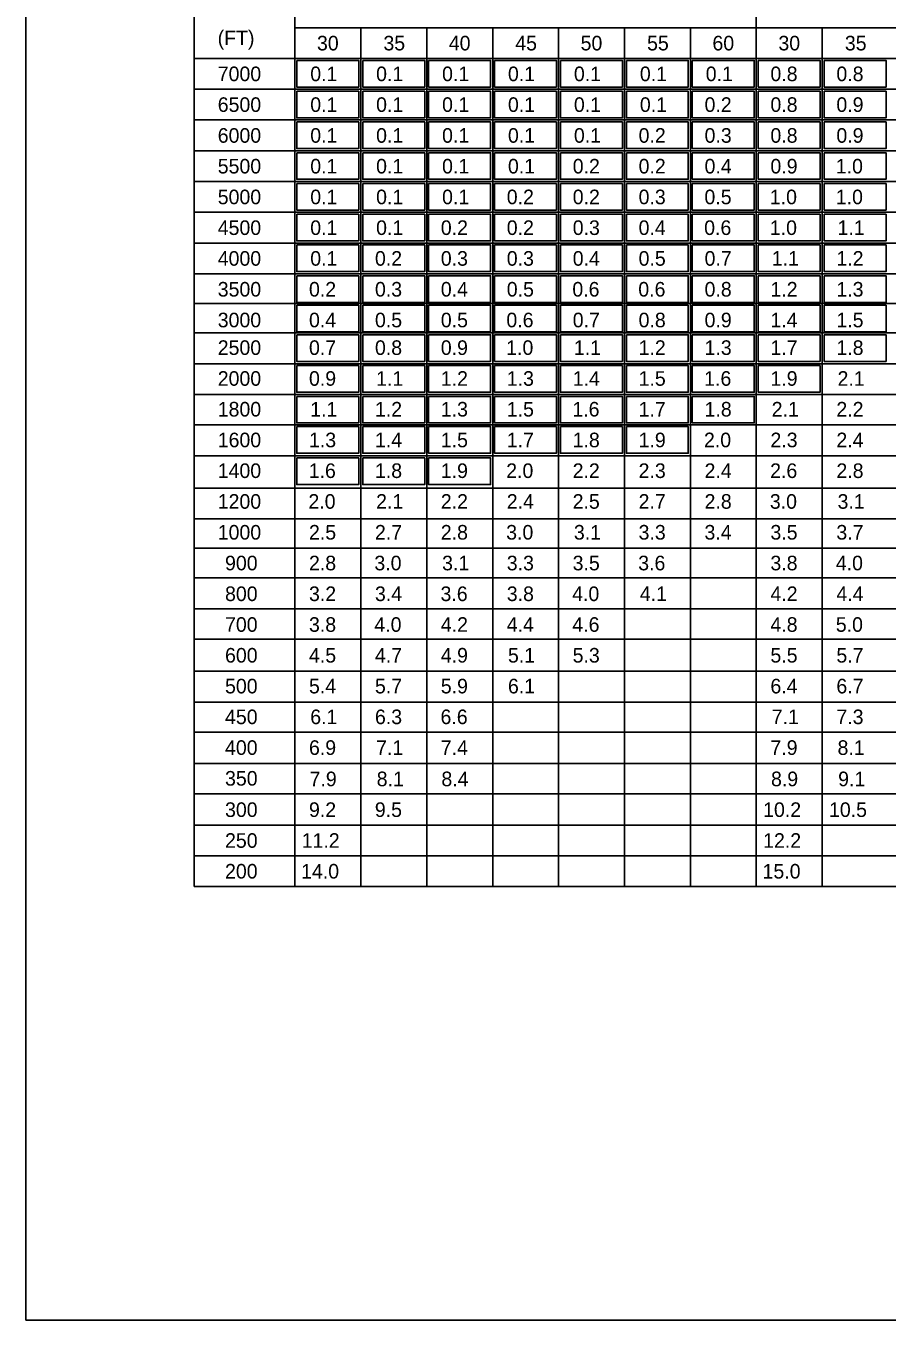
# Model space of a CAD drawing. Extents: x -439.1 to -407.9, y -458.1 to -437.7.
# Drawn here: x -439.11 to -430.26, y -458.05 to -444.75 of the extents above; entities that cross this region are included whole.
import ezdxf

# ---------------------------------------------------------------- set-up
doc = ezdxf.new("R2010")
doc.units = 0
for name, color, linetype in [('Bridge-Named Boundary', 7, 'Continuous'), ('Common-Notes', 7, 'Continuous'), ('Level 4', 7, 'Continuous')]:
    doc.layers.add(name, color=color, linetype=linetype)

msp = doc.modelspace()

# ---------------------------------------------------------------- linework, layer by layer
at = {"layer": 'Bridge-Named Boundary'}
msp.add_lwpolyline([(-439.109, -458.051), (-407.859, -458.051), (-407.859, -437.676), (-439.109, -437.676)], close=True, dxfattribs=at)
at = {"layer": 'Level 4'}
for p, q in [((-437.38, -443.186), (-437.38, -453.595)), ((-436.344, -444.134), (-436.344, -453.595)), ((-431.601, -444.134), (-431.601, -453.595)), ((-436.344, -444.767), (-422.115, -444.767)), ((-435.666, -444.767), (-435.666, -453.595)), ((-434.989, -444.767), (-434.989, -453.595)), ((-434.311, -444.767), (-434.311, -453.595)), ((-433.634, -444.767), (-433.634, -453.595)), ((-432.956, -444.767), (-432.956, -453.595)), ((-432.279, -444.767), (-432.279, -453.595)), ((-430.923, -444.767), (-430.923, -453.595)), ((-437.38, -445.083), (-422.115, -445.083)), ((-437.38, -445.399), (-422.115, -445.399)), ((-437.38, -445.715), (-422.115, -445.715)), ((-437.38, -446.032), (-422.115, -446.032)), ((-437.38, -446.348), (-422.115, -446.348)), ((-437.38, -446.664), (-422.115, -446.664)), ((-437.38, -446.98), (-422.115, -446.98)), ((-437.38, -447.296), (-422.115, -447.296)), ((-437.38, -447.6), (-422.115, -447.6)), ((-437.38, -447.903), (-422.115, -447.903)), ((-437.38, -448.22), (-422.115, -448.22)), ((-437.38, -448.536), (-422.115, -448.536)), ((-437.38, -448.847), (-422.115, -448.847)), ((-437.38, -449.168), (-422.115, -449.168)), ((-437.38, -449.5), (-422.115, -449.5)), ((-437.38, -449.816), (-422.115, -449.816)), ((-437.38, -450.117), (-422.115, -450.117)), ((-437.38, -450.422), (-422.115, -450.422)), ((-437.38, -450.739), (-422.115, -450.739)), ((-437.38, -451.05), (-422.115, -451.05)), ((-437.38, -451.382), (-422.115, -451.382)), ((-437.38, -451.698), (-422.115, -451.698)), ((-437.38, -452.009), (-422.115, -452.009)), ((-437.38, -452.33), (-422.115, -452.33)), ((-437.38, -452.64), (-422.115, -452.64)), ((-437.38, -452.963), (-422.115, -452.963)), ((-437.38, -453.279), (-422.115, -453.279)), ((-437.38, -453.595), (-422.115, -453.595))]:
    msp.add_line(p, q, dxfattribs=at)
for points in [[(-436.324, -445.103), (-435.688, -445.103), (-435.688, -445.377), (-436.324, -445.377)], [(-435.646, -445.103), (-435.01, -445.103), (-435.01, -445.377), (-435.646, -445.377)], [(-434.969, -445.103), (-434.333, -445.103), (-434.333, -445.377), (-434.969, -445.377)], [(-434.291, -445.103), (-433.655, -445.103), (-433.655, -445.377), (-434.291, -445.377)], [(-433.614, -445.103), (-432.978, -445.103), (-432.978, -445.377), (-433.614, -445.377)], [(-432.936, -445.103), (-432.3, -445.103), (-432.3, -445.377), (-432.936, -445.377)], [(-432.259, -445.103), (-431.623, -445.103), (-431.623, -445.377), (-432.259, -445.377)], [(-431.581, -445.103), (-430.945, -445.103), (-430.945, -445.377), (-431.581, -445.377)], [(-430.903, -445.103), (-430.267, -445.103), (-430.267, -445.377), (-430.903, -445.377)], [(-436.324, -445.419), (-435.688, -445.419), (-435.688, -445.693), (-436.324, -445.693)], [(-435.646, -445.419), (-435.01, -445.419), (-435.01, -445.693), (-435.646, -445.693)], [(-434.969, -445.419), (-434.333, -445.419), (-434.333, -445.693), (-434.969, -445.693)], [(-434.291, -445.419), (-433.655, -445.419), (-433.655, -445.693), (-434.291, -445.693)], [(-433.614, -445.419), (-432.978, -445.419), (-432.978, -445.693), (-433.614, -445.693)], [(-432.936, -445.419), (-432.3, -445.419), (-432.3, -445.693), (-432.936, -445.693)], [(-432.259, -445.419), (-431.623, -445.419), (-431.623, -445.693), (-432.259, -445.693)], [(-431.581, -445.419), (-430.945, -445.419), (-430.945, -445.693), (-431.581, -445.693)], [(-430.903, -445.419), (-430.267, -445.419), (-430.267, -445.693), (-430.903, -445.693)], [(-436.324, -445.735), (-435.688, -445.735), (-435.688, -446.009), (-436.324, -446.009)], [(-435.646, -445.735), (-435.01, -445.735), (-435.01, -446.009), (-435.646, -446.009)], [(-434.969, -445.735), (-434.333, -445.735), (-434.333, -446.009), (-434.969, -446.009)], [(-434.291, -445.735), (-433.655, -445.735), (-433.655, -446.009), (-434.291, -446.009)], [(-433.614, -445.735), (-432.978, -445.735), (-432.978, -446.009), (-433.614, -446.009)], [(-432.936, -445.735), (-432.3, -445.735), (-432.3, -446.009), (-432.936, -446.009)], [(-432.259, -445.735), (-431.623, -445.735), (-431.623, -446.009), (-432.259, -446.009)], [(-431.581, -445.735), (-430.945, -445.735), (-430.945, -446.009), (-431.581, -446.009)], [(-430.903, -445.735), (-430.267, -445.735), (-430.267, -446.009), (-430.903, -446.009)], [(-436.324, -446.052), (-435.688, -446.052), (-435.688, -446.325), (-436.324, -446.325)], [(-435.646, -446.052), (-435.01, -446.052), (-435.01, -446.325), (-435.646, -446.325)], [(-434.969, -446.052), (-434.333, -446.052), (-434.333, -446.325), (-434.969, -446.325)], [(-434.291, -446.052), (-433.655, -446.052), (-433.655, -446.325), (-434.291, -446.325)], [(-433.614, -446.052), (-432.978, -446.052), (-432.978, -446.325), (-433.614, -446.325)], [(-432.936, -446.052), (-432.3, -446.052), (-432.3, -446.325), (-432.936, -446.325)], [(-432.259, -446.052), (-431.623, -446.052), (-431.623, -446.325), (-432.259, -446.325)], [(-431.581, -446.052), (-430.945, -446.052), (-430.945, -446.325), (-431.581, -446.325)], [(-430.903, -446.052), (-430.267, -446.052), (-430.267, -446.325), (-430.903, -446.325)], [(-436.324, -446.368), (-435.688, -446.368), (-435.688, -446.642), (-436.324, -446.642)], [(-435.646, -446.368), (-435.01, -446.368), (-435.01, -446.642), (-435.646, -446.642)], [(-434.969, -446.368), (-434.333, -446.368), (-434.333, -446.642), (-434.969, -446.642)], [(-434.291, -446.368), (-433.655, -446.368), (-433.655, -446.642), (-434.291, -446.642)], [(-433.614, -446.368), (-432.978, -446.368), (-432.978, -446.642), (-433.614, -446.642)], [(-432.936, -446.368), (-432.3, -446.368), (-432.3, -446.642), (-432.936, -446.642)], [(-432.259, -446.368), (-431.623, -446.368), (-431.623, -446.642), (-432.259, -446.642)], [(-431.581, -446.368), (-430.945, -446.368), (-430.945, -446.642), (-431.581, -446.642)], [(-430.903, -446.368), (-430.267, -446.368), (-430.267, -446.642), (-430.903, -446.642)], [(-436.324, -446.684), (-435.688, -446.684), (-435.688, -446.958), (-436.324, -446.958)], [(-435.646, -446.684), (-435.01, -446.684), (-435.01, -446.958), (-435.646, -446.958)], [(-434.969, -446.684), (-434.333, -446.684), (-434.333, -446.958), (-434.969, -446.958)], [(-434.291, -446.684), (-433.655, -446.684), (-433.655, -446.958), (-434.291, -446.958)], [(-433.614, -446.684), (-432.978, -446.684), (-432.978, -446.958), (-433.614, -446.958)], [(-432.936, -446.684), (-432.3, -446.684), (-432.3, -446.958), (-432.936, -446.958)], [(-432.259, -446.684), (-431.623, -446.684), (-431.623, -446.958), (-432.259, -446.958)], [(-431.581, -446.684), (-430.945, -446.684), (-430.945, -446.958), (-431.581, -446.958)], [(-430.903, -446.684), (-430.267, -446.684), (-430.267, -446.958), (-430.903, -446.958)], [(-436.324, -447), (-435.688, -447), (-435.688, -447.274), (-436.324, -447.274)], [(-435.646, -447), (-435.01, -447), (-435.01, -447.274), (-435.646, -447.274)], [(-434.969, -447), (-434.333, -447), (-434.333, -447.274), (-434.969, -447.274)], [(-434.291, -447), (-433.655, -447), (-433.655, -447.274), (-434.291, -447.274)], [(-433.614, -447), (-432.978, -447), (-432.978, -447.274), (-433.614, -447.274)], [(-432.936, -447), (-432.3, -447), (-432.3, -447.274), (-432.936, -447.274)], [(-432.259, -447), (-431.623, -447), (-431.623, -447.274), (-432.259, -447.274)], [(-431.581, -447), (-430.945, -447), (-430.945, -447.274), (-431.581, -447.274)], [(-430.903, -447), (-430.267, -447), (-430.267, -447.274), (-430.903, -447.274)], [(-436.324, -447.316), (-435.688, -447.316), (-435.688, -447.59), (-436.324, -447.59)], [(-435.646, -447.316), (-435.01, -447.316), (-435.01, -447.59), (-435.646, -447.59)], [(-434.969, -447.316), (-434.333, -447.316), (-434.333, -447.59), (-434.969, -447.59)], [(-434.291, -447.316), (-433.655, -447.316), (-433.655, -447.59), (-434.291, -447.59)], [(-433.614, -447.316), (-432.978, -447.316), (-432.978, -447.59), (-433.614, -447.59)], [(-432.936, -447.316), (-432.3, -447.316), (-432.3, -447.59), (-432.936, -447.59)], [(-432.259, -447.316), (-431.623, -447.316), (-431.623, -447.59), (-432.259, -447.59)], [(-431.581, -447.316), (-430.945, -447.316), (-430.945, -447.59), (-431.581, -447.59)], [(-430.903, -447.316), (-430.267, -447.316), (-430.267, -447.59), (-430.903, -447.59)], [(-436.324, -447.62), (-435.688, -447.62), (-435.688, -447.894), (-436.324, -447.894)], [(-435.646, -447.62), (-435.01, -447.62), (-435.01, -447.894), (-435.646, -447.894)], [(-434.969, -447.62), (-434.333, -447.62), (-434.333, -447.894), (-434.969, -447.894)], [(-434.291, -447.62), (-433.655, -447.62), (-433.655, -447.894), (-434.291, -447.894)], [(-433.614, -447.62), (-432.978, -447.62), (-432.978, -447.894), (-433.614, -447.894)], [(-432.936, -447.62), (-432.3, -447.62), (-432.3, -447.894), (-432.936, -447.894)], [(-432.259, -447.62), (-431.623, -447.62), (-431.623, -447.894), (-432.259, -447.894)], [(-431.581, -447.62), (-430.945, -447.62), (-430.945, -447.894), (-431.581, -447.894)], [(-430.903, -447.62), (-430.267, -447.62), (-430.267, -447.894), (-430.903, -447.894)], [(-436.324, -447.923), (-435.688, -447.923), (-435.688, -448.197), (-436.324, -448.197)], [(-435.646, -447.923), (-435.01, -447.923), (-435.01, -448.197), (-435.646, -448.197)], [(-434.969, -447.923), (-434.333, -447.923), (-434.333, -448.197), (-434.969, -448.197)], [(-434.291, -447.923), (-433.655, -447.923), (-433.655, -448.197), (-434.291, -448.197)], [(-433.614, -447.923), (-432.978, -447.923), (-432.978, -448.197), (-433.614, -448.197)], [(-432.936, -447.923), (-432.3, -447.923), (-432.3, -448.197), (-432.936, -448.197)], [(-432.259, -447.923), (-431.623, -447.923), (-431.623, -448.197), (-432.259, -448.197)], [(-431.581, -447.923), (-430.945, -447.923), (-430.945, -448.197), (-431.581, -448.197)], [(-430.903, -447.923), (-430.267, -447.923), (-430.267, -448.197), (-430.903, -448.197)], [(-436.324, -448.24), (-435.688, -448.24), (-435.688, -448.513), (-436.324, -448.513)], [(-435.646, -448.24), (-435.01, -448.24), (-435.01, -448.513), (-435.646, -448.513)], [(-434.969, -448.24), (-434.333, -448.24), (-434.333, -448.513), (-434.969, -448.513)], [(-434.291, -448.24), (-433.655, -448.24), (-433.655, -448.513), (-434.291, -448.513)], [(-433.614, -448.24), (-432.978, -448.24), (-432.978, -448.513), (-433.614, -448.513)], [(-432.936, -448.24), (-432.3, -448.24), (-432.3, -448.513), (-432.936, -448.513)], [(-432.259, -448.24), (-431.623, -448.24), (-431.623, -448.513), (-432.259, -448.513)], [(-431.581, -448.24), (-430.945, -448.24), (-430.945, -448.513), (-431.581, -448.513)], [(-436.324, -448.556), (-435.688, -448.556), (-435.688, -448.829), (-436.324, -448.829)], [(-435.646, -448.556), (-435.01, -448.556), (-435.01, -448.829), (-435.646, -448.829)], [(-434.969, -448.556), (-434.333, -448.556), (-434.333, -448.829), (-434.969, -448.829)], [(-434.291, -448.556), (-433.655, -448.556), (-433.655, -448.829), (-434.291, -448.829)], [(-433.614, -448.556), (-432.978, -448.556), (-432.978, -448.829), (-433.614, -448.829)], [(-432.936, -448.556), (-432.3, -448.556), (-432.3, -448.829), (-432.936, -448.829)], [(-432.259, -448.556), (-431.623, -448.556), (-431.623, -448.829), (-432.259, -448.829)], [(-436.324, -448.867), (-435.688, -448.867), (-435.688, -449.141), (-436.324, -449.141)], [(-435.646, -448.867), (-435.01, -448.867), (-435.01, -449.141), (-435.646, -449.141)], [(-434.969, -448.867), (-434.333, -448.867), (-434.333, -449.141), (-434.969, -449.141)], [(-434.291, -448.867), (-433.655, -448.867), (-433.655, -449.141), (-434.291, -449.141)], [(-433.614, -448.867), (-432.978, -448.867), (-432.978, -449.141), (-433.614, -449.141)], [(-432.936, -448.867), (-432.3, -448.867), (-432.3, -449.141), (-432.936, -449.141)], [(-436.324, -449.188), (-435.688, -449.188), (-435.688, -449.462), (-436.324, -449.462)], [(-435.646, -449.188), (-435.01, -449.188), (-435.01, -449.462), (-435.646, -449.462)], [(-434.969, -449.188), (-434.333, -449.188), (-434.333, -449.462), (-434.969, -449.462)]]:
    msp.add_lwpolyline(points, close=True, dxfattribs=at)

# ---------------------------------------------------------------- texts
at = {"layer": 'Common-Notes'}
for s, p in [('(FT)', (-437.138, -444.946)), ('30', (-436.117, -445)), ('35', (-435.434, -445)), ('40', (-434.762, -445)), ('45', (-434.079, -445)), ('50', (-433.407, -445)), ('55', (-432.724, -445)), ('60', (-432.052, -445)), ('30', (-431.374, -445)), ('35', (-430.691, -445)), ('7000', (-437.137, -445.316)), ('0.1', (-436.186, -445.316)), ('0.1', (-435.509, -445.316)), ('0.1', (-434.831, -445.316)), ('0.1', (-434.154, -445.316)), ('0.1', (-433.476, -445.316)), ('0.1', (-432.798, -445.316)), ('0.1', (-432.121, -445.316)), ('0.8', (-431.456, -445.316)), ('0.8', (-430.778, -445.316)), ('6500', (-437.137, -445.632)), ('0.1', (-436.186, -445.632)), ('0.1', (-435.509, -445.632)), ('0.1', (-434.831, -445.632)), ('0.1', (-434.154, -445.632)), ('0.1', (-433.476, -445.632)), ('0.1', (-432.798, -445.632)), ('0.2', (-432.133, -445.632)), ('0.8', (-431.456, -445.632)), ('0.9', (-430.778, -445.632)), ('6000', (-437.137, -445.949)), ('0.1', (-436.186, -445.949)), ('0.1', (-435.509, -445.949)), ('0.1', (-434.831, -445.949)), ('0.1', (-434.154, -445.949)), ('0.1', (-433.476, -445.949)), ('0.2', (-432.811, -445.949)), ('0.3', (-432.133, -445.949)), ('0.8', (-431.456, -445.949)), ('0.9', (-430.778, -445.949)), ('5500', (-437.137, -446.265)), ('0.1', (-436.186, -446.265)), ('0.1', (-435.509, -446.265)), ('0.1', (-434.831, -446.265)), ('0.1', (-434.154, -446.265)), ('0.2', (-433.488, -446.265)), ('0.2', (-432.811, -446.265)), ('0.4', (-432.133, -446.265)), ('0.9', (-431.456, -446.265)), ('1.0', (-430.784, -446.265)), ('5000', (-437.137, -446.581)), ('0.1', (-436.186, -446.581)), ('0.1', (-435.509, -446.581)), ('0.1', (-434.831, -446.581)), ('0.2', (-434.166, -446.581)), ('0.2', (-433.488, -446.581)), ('0.3', (-432.811, -446.581)), ('0.5', (-432.134, -446.581)), ('1.0', (-431.462, -446.581)), ('1.0', (-430.784, -446.581)), ('4500', (-437.137, -446.897)), ('0.1', (-436.186, -446.897)), ('0.1', (-435.509, -446.897)), ('0.2', (-434.844, -446.897)), ('0.2', (-434.166, -446.897)), ('0.3', (-433.488, -446.897)), ('0.4', (-432.811, -446.897)), ('0.6', (-432.137, -446.897)), ('1.0', (-431.462, -446.897)), ('1.1', (-430.766, -446.897)), ('4000', (-437.137, -447.213)), ('0.1', (-436.186, -447.213)), ('0.2', (-435.521, -447.213)), ('0.3', (-434.844, -447.213)), ('0.3', (-434.166, -447.213)), ('0.4', (-433.488, -447.213)), ('0.5', (-432.811, -447.213)), ('0.7', (-432.133, -447.213)), ('1.1', (-431.443, -447.213)), ('1.2', (-430.778, -447.213)), ('3500', (-437.137, -447.53)), ('0.2', (-436.199, -447.53)), ('0.3', (-435.521, -447.53)), ('0.4', (-434.844, -447.53)), ('0.5', (-434.166, -447.53)), ('0.6', (-433.492, -447.53)), ('0.6', (-432.814, -447.53)), ('0.8', (-432.133, -447.53)), ('1.2', (-431.456, -447.53)), ('1.3', (-430.778, -447.53)), ('3000', (-437.137, -447.846)), ('0.4', (-436.199, -447.846)), ('0.5', (-435.521, -447.846)), ('0.5', (-434.844, -447.846)), ('0.6', (-434.17, -447.846)), ('0.7', (-433.488, -447.846)), ('0.8', (-432.811, -447.846)), ('0.9', (-432.133, -447.846)), ('1.4', (-431.456, -447.846)), ('1.5', (-430.778, -447.846)), ('2500', (-437.137, -448.13)), ('0.7', (-436.199, -448.13)), ('0.8', (-435.521, -448.13)), ('0.9', (-434.844, -448.13)), ('1.0', (-434.172, -448.13)), ('1.1', (-433.476, -448.13)), ('1.2', (-432.811, -448.13)), ('1.3', (-432.133, -448.13)), ('1.7', (-431.456, -448.13)), ('1.8', (-430.778, -448.13)), ('2000', (-437.137, -448.447)), ('0.9', (-436.199, -448.447)), ('1.1', (-435.509, -448.447)), ('1.2', (-434.844, -448.447)), ('1.3', (-434.166, -448.447)), ('1.4', (-433.488, -448.447)), ('1.5', (-432.811, -448.447)), ('1.6', (-432.137, -448.447)), ('1.9', (-431.456, -448.447)), ('2.1', (-430.766, -448.447)), ('1800', (-437.137, -448.763)), ('1.1', (-436.186, -448.763)), ('1.2', (-435.521, -448.763)), ('1.3', (-434.844, -448.763)), ('1.5', (-434.166, -448.763)), ('1.6', (-433.492, -448.763)), ('1.7', (-432.811, -448.763)), ('1.8', (-432.133, -448.763)), ('2.1', (-431.443, -448.763)), ('2.2', (-430.778, -448.763)), ('1600', (-437.137, -449.079)), ('1.3', (-436.199, -449.079)), ('1.4', (-435.521, -449.079)), ('1.5', (-434.844, -449.079)), ('1.7', (-434.166, -449.079)), ('1.8', (-433.489, -449.079)), ('1.9', (-432.811, -449.079)), ('2.0', (-432.139, -449.079)), ('2.3', (-431.456, -449.079)), ('2.4', (-430.778, -449.079)), ('1400', (-437.137, -449.395)), ('1.6', (-436.202, -449.395)), ('1.8', (-435.521, -449.395)), ('1.9', (-434.844, -449.395)), ('2.0', (-434.172, -449.395)), ('2.2', (-433.489, -449.395)), ('2.3', (-432.811, -449.395)), ('2.4', (-432.133, -449.395)), ('2.6', (-431.459, -449.395)), ('2.8', (-430.778, -449.395)), ('1200', (-437.137, -449.711)), ('2.0', (-436.205, -449.711)), ('2.1', (-435.509, -449.711)), ('2.2', (-434.844, -449.711)), ('2.4', (-434.166, -449.711)), ('2.5', (-433.489, -449.711)), ('2.7', (-432.811, -449.711)), ('2.8', (-432.133, -449.711)), ('3.0', (-431.462, -449.711)), ('3.1', (-430.766, -449.711)), ('1000', (-437.137, -450.028)), ('2.5', (-436.199, -450.028)), ('2.7', (-435.521, -450.028)), ('2.8', (-434.844, -450.028)), ('3.0', (-434.172, -450.028)), ('3.1', (-433.476, -450.028)), ('3.3', (-432.811, -450.028)), ('3.4', (-432.134, -450.028)), ('3.5', (-431.456, -450.028)), ('3.7', (-430.778, -450.028)), ('900', (-437.062, -450.344)), ('2.8', (-436.199, -450.344)), ('3.0', (-435.527, -450.344)), ('3.1', (-434.831, -450.344)), ('3.3', (-434.166, -450.344)), ('3.5', (-433.489, -450.344)), ('3.6', (-432.815, -450.344)), ('3.8', (-431.456, -450.344)), ('4.0', (-430.784, -450.344)), ('800', (-437.062, -450.66)), ('3.2', (-436.199, -450.66)), ('3.4', (-435.521, -450.66)), ('3.6', (-434.847, -450.66)), ('3.8', (-434.166, -450.66)), ('4.0', (-433.494, -450.66)), ('4.1', (-432.799, -450.66)), ('4.2', (-431.456, -450.66)), ('4.4', (-430.778, -450.66)), ('700', (-437.062, -450.976)), ('3.8', (-436.199, -450.976)), ('4.0', (-435.527, -450.976)), ('4.2', (-434.844, -450.976)), ('4.4', (-434.166, -450.976)), ('4.6', (-433.492, -450.976)), ('4.8', (-431.456, -450.976)), ('5.0', (-430.784, -450.976)), ('600', (-437.062, -451.292)), ('4.5', (-436.199, -451.292)), ('4.7', (-435.521, -451.292)), ('4.9', (-434.844, -451.292)), ('5.1', (-434.154, -451.292)), ('5.3', (-433.489, -451.292)), ('5.5', (-431.456, -451.292)), ('5.7', (-430.778, -451.292)), ('500', (-437.062, -451.609)), ('5.4', (-436.199, -451.609)), ('5.7', (-435.521, -451.609)), ('5.9', (-434.844, -451.609)), ('6.1', (-434.154, -451.609)), ('6.4', (-431.456, -451.609)), ('6.7', (-430.778, -451.609)), ('450', (-437.062, -451.925)), ('6.1', (-436.186, -451.925)), ('6.3', (-435.521, -451.925)), ('6.6', (-434.847, -451.925)), ('7.1', (-431.443, -451.925)), ('7.3', (-430.778, -451.925)), ('400', (-437.062, -452.241)), ('6.9', (-436.199, -452.241)), ('7.1', (-435.509, -452.241)), ('7.4', (-434.844, -452.241)), ('7.9', (-431.456, -452.241)), ('8.1', (-430.766, -452.241)), ('350', (-437.062, -452.557)), ('7.9', (-436.193, -452.563)), ('8.1', (-435.503, -452.563)), ('8.4', (-434.838, -452.563)), ('8.9', (-431.45, -452.563)), ('9.1', (-430.76, -452.563)), ('300', (-437.062, -452.879)), ('9.2', (-436.199, -452.879)), ('9.5', (-435.522, -452.879)), ('10.2', (-431.531, -452.879)), ('10.5', (-430.854, -452.879)), ('250', (-437.062, -453.196)), ('11.2', (-436.274, -453.196)), ('12.2', (-431.531, -453.196)), ('200', (-437.062, -453.512)), ('14.0', (-436.28, -453.512)), ('15.0', (-431.537, -453.512))]:
    msp.add_text(s, height=0.15, dxfattribs=at).set_placement(p)

doc.saveas('drawing.dxf')
